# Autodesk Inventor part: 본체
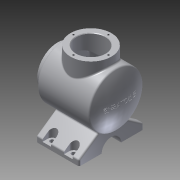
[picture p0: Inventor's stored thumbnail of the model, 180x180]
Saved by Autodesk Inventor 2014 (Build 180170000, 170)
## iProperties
Created: 2017-04
Part Number: 본체
Material: 알루미늄 6061
Document SubType Name: Modeling
Designer: user
Density: 2.71 g/cm^3
Appearance: 알루미늄 - 평지
Mass: 1669.39 g
Surface Area: 1069.84 cm^2
Volume: 616.012 cm^3
Author: user
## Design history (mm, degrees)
sketch "스케치1"
  geometry: L1 (-54, 0)-(54, 0); L2 (-54, 0)-(-54, 50); L3 (-54, 50)-(42.336, 50); A1 r 113 centre (-59, 0) between (54, 0) and (42.336, 50); 2 further points
  constraints: 6 end point, 2 perpendicular, 2 point on circle, 1 centre point, 1 coincident, 1 horizontal, 1 horizontal alignment, 1 midpoint
  dimensions: "d1" = 113 radius of A1; "d2" = 108 distance from line of L1.end L2; "d3" = 100 diameter of L3 L1
revolve "회전1" sketch "스케치1" stored, may be unused: angle "d4" = 90 deg
sketch "스케치2"
  geometry: C1 r 50 at (0, 0) reference; C2 r 38 at (0, 0)
  constraints: 1 centre point, 1 coincident
  dimensions: "d5" = 76 diameter of C2
extrude "돌출1" join sketch "스케치2" distance "d6" = 12; taper "d7" = 0 deg
node "작업 평면1"
sketch "스케치3"
  geometry: L1 (-45.101, 21.584)-(-72, 60); L2 (-72, 60)-(-82, 60); L3 (-82, 60)-(-82, -60); L4 (-82, -60)-(-72, -60); L5 (-72, -60)-(-45.101, -21.584); A1 r 50 centre (0, 0) between (-45.101, 21.584) and (-45.101, -21.584) reference; A2 r 18 centre (-82, 0) between (-82, -18) and (-82, 18); 2 further points
  constraints: 10 end point, 4 point on circle, 2 perpendicular, 2 point on line, 1 centre point, 1 coincident, 1 horizontal, 1 horizontal alignment, 1 midpoint
  dimensions: "d9" = 82 distance from line of point (0, 0) L3; "d10" = 10 distance of L1.end L2.end; "d11" = 10 distance of L3.end L4.end; "d12" = 55 deg angle of L1 L2; "d13" = 55 deg angle of L5 L4; "d14" = 120 distance of L2.end L3.end; "d15" = 36 diameter of A2
extrude "돌출2" join sketch "스케치3" distance "d16" = 80; taper "d17" = 0 deg
node "작업 평면2"
sketch "스케치4"
  geometry: L1 (-8, 10)-(-8, 110) reference; C1 r 38 at (42, 60); 1 further point
  constraints: 1 centre point, 1 horizontal alignment
  dimensions: "d19" = 76 diameter of C1; "d20" = 50 distance from line of C1.centre L1
extrude "돌출3" join sketch "스케치4" stored distance "d21" = 80; taper "d22" = 0 deg
sketch "스케치5"
  geometry: L1 (66, -38)-(66, 38) reference; L2 (66, 0)-(-54, 0); L3 (54, 50)-(-42.336, 50) reference; L4 (54, 50)-(54, -50) reference; L5 (54, 38)-(66, 38) reference; L6 (54, -38)-(66, -38) reference; L7 (54, -50)-(-42.336, -50) reference; L8 (-33.903, 40)-(41, 40); L9 (44, 37)-(44, 27); L10 (44, 27)-(66, 27); A1 r 113 centre (59, 0) between (-42.336, 50) and (-42.336, -50) reference; A2 r 103 centre (59, 0) between (-36.69, 38.11) and (-44, 0); A3 r 3 centre (-33.903, 37) between (-33.903, 40) and (-36.69, 38.11); A4 r 3 centre (41, 37) between (44, 37) and (41, 40); 2 further points
  constraints: 8 end point, 8 point on circle, 4 tangent, 3 centre point, 3 point on line, 1 equal radius, 1 midpoint, 1 perpendicular
  dimensions: "d23" = 10 radial gap between concentric circles of A2 A1; "d24" = 10 distance between parallel lines of L8 L3; "d25" = 80 diameter of L8 L2 (derived); "d26" = 10 distance between parallel lines of L9 L4; "d27" = 54 diameter of L10 L2; "d28" = 3 radius of A3; "d44" = 22 distance of L9.end L10.end (derived)
revolve "회전2" sketch "스케치5" stored, may be unused: angle "d29" = 90 deg
sketch "스케치6"
  geometry: C1 r 38 at (0, 0) reference; C2 r 27 at (0, 0); 1 further point
  constraints: 1 centre point, 1 coincident
  dimensions: "d30" = 54 diameter of C2
extrude "돌출4" cut sketch "스케치6" stored distance "d31" = 80; taper "d32" = 0 deg
sketch "스케치7"
  geometry: C1 r 27 at (0, 0) reference; C2 r 38 at (0, 0) reference; A1 r 32.5 centre (0, 0) between (0, 32.5) and (-32.5, 0); 3 further points
  constraints: 4 point on circle, 2 horizontal alignment, 2 vertical alignment, 1 centre point, 1 coincident
  dimensions: "d33" = 65 diameter of A1
hole "구멍1" sketch "스케치7" at (0, 32.5), (-32.5, 0), (32.5, 0), (0, -32.5) diameter "d34" = 3.242; stored, may be unused: countersink angle "d38" = 90 deg, drill point angle "d40" = 118 deg; dims "d35" = 8, "d36" = 4, "d37" = 2, "d39" = 10
chamfer "모따기1" distance "d41" = 1; stored, may be unused: second distance "d42" = 2, angle "d43" = 45 deg
sketch "스케치8"
  geometry: C1 r 38 at (0, 0) reference; C2 r 28 at (0, 0) reference; A1 r 32.5 centre (0, 0) between (0, 32.5) and (32.5, 0); 2 further points
  constraints: 4 point on circle, 2 horizontal alignment, 2 vertical alignment, 1 centre point, 1 coincident
  dimensions: "d45" = 65 diameter of A1
hole "구멍2" sketch "스케치8" at (0, 32.5), (32.5, 0), (0, -32.5), (-32.5, 0) diameter "d46" = 3.242; stored, may be unused: countersink angle "d50" = 90 deg, drill point angle "d52" = 118 deg; dims "d47" = 8, "d48" = 4, "d49" = 2, "d51" = 10
node "작업 평면3"
sketch "스케치9"
  geometry: L1 (80, 0)-(80, 42) reference; L2 (0, 0)-(80, 0) reference; L3 (12, 10)-(12, 0); L4 (28, 10)-(28, 0); L5 (52, 10)-(52, 0); L6 (68, 10)-(68, 0); A1 r 8 centre (60, 10) between (68, 10) and (52, 10); A2 r 8 centre (20, 10) between (28, 10) and (12, 10); 1 further point
  constraints: 8 end point, 4 point on circle, 4 point on line, 4 tangent, 3 perpendicular, 2 centre point, 1 horizontal alignment, 1 parallel
  dimensions: "d54" = 16 diameter of A1; "d55" = 16 diameter of A2; "d56" = 40 distance of A1.centre A2.centre; "d57" = 20 distance from line of A1.centre L1; "d58" = 10 distance from line of A1.centre L2
extrude "돌출5" cut sketch "스케치9" stored distance "d59" = 80; taper "d60" = 0 deg
hole "구멍3" diameter "d63" = 8; stored, may be unused: countersink angle "d67" = 90 deg, drill point angle "d69" = 118 deg; dims "d61" = 10, "d62" = 10, "d64" = 8, "d65" = 4, "d66" = 2, "d68" = 10
hole "구멍4" diameter "d72" = 8; stored, may be unused: countersink angle "d76" = 90 deg, drill point angle "d78" = 118 deg; dims "d70" = 10, "d71" = 10, "d73" = 8, "d74" = 4, "d75" = 2, "d77" = 10
node "작업 평면4"
sketch "스케치10"
  geometry: 2 further points
  constraints: 1 coincident, 1 other
feature "엠보싱1" sketch "스케치10" dims "d1" = 113, "d2" = 108, "d3" = 100, "d79" = 0.5, "d80" = 0
chamfer "모따기2" distance "d81" = 1; stored, may be unused: second distance "d82" = 2, angle "d83" = 45 deg
fillet "모깎기1" dims "d84" = 3
fillet "모깎기2" dims "d85" = 3
fillet "모깎기3" dims "d86" = 3
fillet "모깎기4" dims "d87" = 3
fillet "모깎기5" dims "d88" = 3
fillet "모깎기6" dims "d89" = 3
fillet "모깎기7" dims "d90" = 3
node "솔리드1"
mirror "대칭1"
mirror "대칭2"
other parameters: "d8" = -8, "d18" = -147, "d53" = -6
